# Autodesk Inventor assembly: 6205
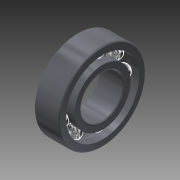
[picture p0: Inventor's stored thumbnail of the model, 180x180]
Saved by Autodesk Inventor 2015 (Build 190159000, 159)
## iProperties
Company: TraceParts S.A.
Created: 2012-12
Part Number: 6205
Checked By: TraceParts S.A.
Catalog Web Link: www.traceparts.com
Description: Radial ball bearing
Vendor: Schaeffler Technologies AG & Co. KG
Document SubType Name: Assembly
Designer: TraceParts
DESIGN: Radial ball bearing
REFERENCE: 6205
SELECTION: 6205
SUPPLIER: Schaeffler Technologies AG & Co. KG
Title: Radial ball bearing
Author: TraceParts
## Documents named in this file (12)
- C:\Users\Andrew Almeida\Documents\Projeto WS2015\WS2015 CAD Data ANLAS\01\Pneumatic System\Engine\Pneumatikus hajtás\Csapágy\inafag_6205_1vmsegths975f8cvzct4fnofv.iam
- C:\Users\Andrew Almeida\Documents\Projeto WS2015\WS2015 CAD Data ANLAS\01\Pneumatic System\Engine\Pneumatikus hajtás\Csapágy\inafag_6205_1vmsegths975f8cvzct4fnofv_11.ipt
- C:\Users\Andrew Almeida\Documents\Projeto WS2015\WS2015 CAD Data ANLAS\01\Pneumatic System\Engine\Pneumatikus hajtás\Csapágy\inafag_6205_1vmsegths975f8cvzct4fnofv_10.ipt
- C:\Users\Andrew Almeida\Documents\Projeto WS2015\WS2015 CAD Data ANLAS\01\Pneumatic System\Engine\Pneumatikus hajtás\Csapágy\inafag_6205_1vmsegths975f8cvzct4fnofv_09.ipt
- C:\Users\Andrew Almeida\Documents\Projeto WS2015\WS2015 CAD Data ANLAS\01\Pneumatic System\Engine\Pneumatikus hajtás\Csapágy\inafag_6205_1vmsegths975f8cvzct4fnofv_08.ipt
- C:\Users\Andrew Almeida\Documents\Projeto WS2015\WS2015 CAD Data ANLAS\01\Pneumatic System\Engine\Pneumatikus hajtás\Csapágy\inafag_6205_1vmsegths975f8cvzct4fnofv_07.ipt
- C:\Users\Andrew Almeida\Documents\Projeto WS2015\WS2015 CAD Data ANLAS\01\Pneumatic System\Engine\Pneumatikus hajtás\Csapágy\inafag_6205_1vmsegths975f8cvzct4fnofv_06.ipt
- C:\Users\Andrew Almeida\Documents\Projeto WS2015\WS2015 CAD Data ANLAS\01\Pneumatic System\Engine\Pneumatikus hajtás\Csapágy\inafag_6205_1vmsegths975f8cvzct4fnofv_05.ipt
- C:\Users\Andrew Almeida\Documents\Projeto WS2015\WS2015 CAD Data ANLAS\01\Pneumatic System\Engine\Pneumatikus hajtás\Csapágy\inafag_6205_1vmsegths975f8cvzct4fnofv_04.ipt
- C:\Users\Andrew Almeida\Documents\Projeto WS2015\WS2015 CAD Data ANLAS\01\Pneumatic System\Engine\Pneumatikus hajtás\Csapágy\inafag_6205_1vmsegths975f8cvzct4fnofv_03.ipt
- C:\Users\Andrew Almeida\Documents\Projeto WS2015\WS2015 CAD Data ANLAS\01\Pneumatic System\Engine\Pneumatikus hajtás\Csapágy\inafag_6205_1vmsegths975f8cvzct4fnofv_02.ipt
- C:\Users\Andrew Almeida\Documents\Projeto WS2015\WS2015 CAD Data ANLAS\01\Pneumatic System\Engine\Pneumatikus hajtás\Csapágy\inafag_6205_1vmsegths975f8cvzct4fnofv_01.ipt
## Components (11 placed, 11 different names)
1. inafag_6205_1vmsegths975f8cvzct4fnofv_11:1
2. inafag_6205_1vmsegths975f8cvzct4fnofv_10:1
3. inafag_6205_1vmsegths975f8cvzct4fnofv_09:1
4. inafag_6205_1vmsegths975f8cvzct4fnofv_08:1
5. inafag_6205_1vmsegths975f8cvzct4fnofv_07:1
6. inafag_6205_1vmsegths975f8cvzct4fnofv_06:1
7. inafag_6205_1vmsegths975f8cvzct4fnofv_05:1
8. inafag_6205_1vmsegths975f8cvzct4fnofv_04:1
9. inafag_6205_1vmsegths975f8cvzct4fnofv_03:1
10. inafag_6205_1vmsegths975f8cvzct4fnofv_02:1
11. inafag_6205_1vmsegths975f8cvzct4fnofv_01:1
